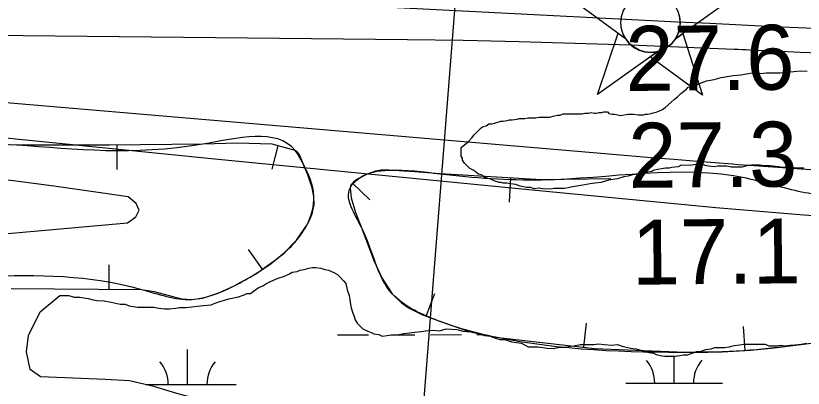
# Model space of a CAD drawing. Extents: x 3361039 to 3398939, y 576572 to 602007.
# Drawn here: x 3381254 to 3382066, y 585360 to 585744 of the extents above; entities that cross this region are included whole.
import ezdxf

# ---------------------------------------------------------------- set-up
doc = ezdxf.new("R2010")
doc.units = 0
for name, color, linetype in [('V-BORW-LINE', 7, 'Continuous'), ('V-CHAN-NAID', 7, 'Continuous'), ('V-RIVR-RANG', 7, 'Continuous'), ('V-SITE-VEGE', 7, 'Continuous'), ('V-TOPO-MAJR', 7, 'Continuous'), ('V-TOPO-MINR', 7, 'Continuous'), ('V-WETL-SWMP', 7, 'Continuous')]:
    doc.layers.add(name, color=color, linetype=linetype)

msp = doc.modelspace()

# ---------------------------------------------------------------- linework, layer by layer
at = {"layer": 'V-BORW-LINE'}
for p, q in [((3381357.75, 585610.77), (3381358.02, 585585.77)), ((3381524.08, 585610.05), (3381517.68, 585585.89)), ((3381601.07, 585571.69), (3381618.95, 585554.22)), ((3381764.16, 585576.87), (3381762.71, 585551.91)), ((3381508.14, 585482.73), (3381493.76, 585503.19)), ((3381349.92, 585462.11), (3381350.05, 585487.11)), ((3381676.92, 585434.33), (3381686.07, 585457.6)), ((3381839.57, 585402.24), (3381842.4, 585427.08)), ((3382005.98, 585398.71), (3382004.47, 585423.66))]:
    msp.add_line(p, q, dxfattribs=at)
for points in [[(3381248.73, 585462.66), (3381383.19, 585461.93), (3381396.24, 585459.77), (3381415.66, 585454.41), (3381425.33, 585452.32), (3381435, 585451.58), (3381446.12, 585452.88), (3381462.55, 585458.05), (3381478.78, 585465.47), (3381501.04, 585477.75), (3381521.69, 585492.26), (3381530.96, 585500.05), (3381543.15, 585512.8), (3381553.85, 585528.16), (3381557.61, 585535.53), (3381559.65, 585541.14), (3381561.33, 585549.58), (3381561.17, 585557.92), (3381559.37, 585566.77), (3381555.01, 585579.98), (3381549.36, 585593.15), (3381546.57, 585600.25), (3381544.67, 585603.3), (3381543.37, 585604.48), (3381541.77, 585605.37), (3381518.01, 585611.66), (3381482.27, 585612.98), (3381446.45, 585611.73), (3381350.4, 585610.69), (3381254.35, 585610.74), (3381248.84, 585611.13)], [(3381867.63, 585576.1), (3381796, 585575.03), (3381743.77, 585578.05), (3381691.54, 585581.2), (3381664.99, 585583.08), (3381638.45, 585584.98), (3381630.52, 585584.79), (3381624.68, 585583.76), (3381616.01, 585580.87), (3381607.38, 585576.47), (3381604.2, 585574.42), (3381602.03, 585572.67), (3381600.63, 585571.24), (3381599.11, 585568.92), (3381598.51, 585566.36), (3381599.48, 585556.45), (3381604.07, 585541.34), (3381610.08, 585526.4), (3381623.21, 585490.87), (3381631.16, 585473.72), (3381641.99, 585457.34), (3381651.47, 585447.98), (3381659.47, 585442.52), (3381672.5, 585436.07), (3381686.19, 585430.69), (3381717.08, 585419.85), (3381748.69, 585412.56), (3381850.72, 585400.97), (3381952.89, 585396.92), (3381982.29, 585397.28), (3382011.65, 585399.05), (3382036.2, 585401.7), (3382060.7, 585404.53), (3382143.48, 585415.45)]]:
    msp.add_lwpolyline(points, dxfattribs=at)
for points in [[(3380614.71, 585699.37), (3380933.86, 585658.54), (3380993.04, 585639.95), (3381254.35, 585610.74), (3381446.45, 585611.73), (3381541.77, 585605.37), (3381549.36, 585593.15), (3381561.17, 585557.92), (3381553.85, 585528.16), (3381521.69, 585492.26), (3381478.78, 585465.47), (3381435, 585451.58), (3381383.19, 585461.93), (3381059.18, 585470.07), (3380726.36, 585534.4), (3380328.5, 585584.44), (3380211.56, 585609.24), (3380158.59, 585613.34), (3380106.57, 585620.06), (3380047.44, 585636.22), (3380016.16, 585668.36), (3379997.02, 585709.42), (3379989.83, 585740.01), (3380003.9, 585755.26), (3380025.63, 585764.58), (3380071.77, 585772.23), (3380236.06, 585747.23), (3380349.15, 585718.45), (3380401.48, 585706.99), (3380505.12, 585707.23), (3380614.71, 585699.37)], [(3382571.75, 585529.85), (3382288.5, 585546.28), (3382119.28, 585556.22), (3382064.39, 585562.69), (3382006.96, 585576.93), (3381796, 585575.03), (3381691.54, 585581.2), (3381638.45, 585584.98), (3381607.38, 585576.47), (3381598.51, 585566.36), (3381610.08, 585526.4), (3381641.99, 585457.34), (3381686.19, 585430.69), (3381748.69, 585412.56), (3381952.89, 585396.92), (3382011.65, 585399.05), (3382060.7, 585404.53), (3382233.38, 585410.22), (3382597.39, 585393.13), (3382822.43, 585377.96), (3382985.12, 585375.03), (3383040.48, 585369.32), (3383111.3, 585349.64), (3383186.01, 585343.18), (3383349.37, 585344.09), (3383670.1, 585328.99), (3383776.96, 585325.83), (3383950.1, 585282.41), (3384048.66, 585281.9), (3384105.28, 585326.49), (3384120.75, 585332.34), (3384160.48, 585298.98), (3384209.82, 585275.27), (3384267.65, 585259.58), (3384373.27, 585255.57), (3384419.94, 585258.58), (3384709.73, 585239.38), (3384826.34, 585210.62), (3384946.51, 585203.35), (3385109.52, 585215.5), (3385207.25, 585213.25), (3385246.28, 585211.98), (3385305.12, 585207.81), (3385479.9, 585187.69), (3385835.24, 585189.26), (3386014.23, 585230.05), (3386056.71, 585240.88), (3386176.62, 585300.03), (3386207.38, 585325.51), (3386221.37, 585345.61), (3386182.35, 585376.31), (3386126.76, 585381.36), (3386029.51, 585369.17), (3385921.06, 585366.42), (3385817.08, 585354.08), (3385761.67, 585353.52), (3385594.41, 585354.59), (3385499.8, 585346.62), (3385375.62, 585344.42), (3385091.32, 585358.84), (3384912.21, 585381.83), (3384861.67, 585385.98), (3384294.69, 585385.71), (3384190.67, 585395.62), (3384128.27, 585377.4), (3384079.07, 585402.54), (3383956.19, 585439.51), (3383615.98, 585443.36), (3383292.93, 585470.42), (3383014.82, 585493.71), (3382867.4, 585507.63), (3382640.11, 585523.01), (3382571.75, 585529.85)]]:
    msp.add_spline(points, degree=3, dxfattribs=at)
at = {"layer": 'V-CHAN-NAID'}
for points in [[(3381821.1, 585766.19), (3381882.67, 585720.79), (3381881.55, 585722.7), (3381880.74, 585724.33), (3381879.92, 585726.3), (3381879.22, 585728.35), (3381878.86, 585729.67), (3381878.5, 585731.3), (3381878.25, 585732.74), (3381878.06, 585734.34), (3381877.95, 585736.08), (3381877.94, 585737.66), (3381878.05, 585739.73), (3381878.23, 585741.35), (3381878.62, 585743.55), (3381879.1, 585745.48)], [(3381996.26, 585764.95), (3381934.06, 585720.43), (3381934.97, 585721.91), (3381935.95, 585723.76), (3381936.66, 585725.35), (3381937.4, 585727.3), (3381937.94, 585729.09), (3381938.34, 585730.73), (3381938.7, 585732.74), (3381938.89, 585734.31), (3381939.01, 585736.51), (3381938.98, 585738.58), (3381938.79, 585740.8), (3381938.53, 585742.55), (3381938.04, 585744.79)]]:
    msp.add_lwpolyline(points, dxfattribs=at)
for points in [[(3381916.02, 585707.52), (3381853.82, 585663), (3381874.95, 585726.48), (3381882.67, 585720.79), (3381883.3, 585719.83), (3381884.68, 585717.97), (3381885.9, 585716.55), (3381887.36, 585715.05), (3381888.75, 585713.8), (3381890.21, 585712.64), (3381891.61, 585711.65), (3381893.29, 585710.62), (3381895, 585709.71), (3381896.79, 585708.9), (3381898.24, 585708.34), (3381899.87, 585707.81), (3381902.09, 585707.25), (3381903.62, 585706.96), (3381905.65, 585706.7), (3381907.19, 585706.6), (3381909.05, 585706.58), (3381910.73, 585706.66), (3381912.45, 585706.83), (3381914.35, 585707.14)], [(3381934.06, 585720.43), (3381941.85, 585726.01), (3381962.08, 585662.23), (3381908.23, 585701.94), (3381916.02, 585707.52), (3381917.69, 585708), (3381919.3, 585708.56), (3381921.46, 585709.47), (3381923.2, 585710.35), (3381925.06, 585711.47), (3381926.8, 585712.68), (3381928.35, 585713.92), (3381929.64, 585715.09), (3381931.02, 585716.51), (3381932.23, 585717.91), (3381933.35, 585719.39)]]:
    msp.add_lwpolyline(points, close=True, dxfattribs=at)
msp.add_circle((3381908.48, 585737.11), 30.54, dxfattribs=at)
at = {"layer": 'V-RIVR-RANG'}
msp.add_line((3381667.9, 585260.79), (3381771, 586569.73), dxfattribs=at)
at = {"layer": 'V-SITE-VEGE'}
for points in [[(3381805.26, 585565.46), (3381797.26, 585565.52), (3381793.62, 585566.27), (3381788.53, 585565.58), (3381784.9, 585567.06), (3381780.54, 585567.09), (3381774, 585568.59), (3381769.65, 585570.08), (3381763.83, 585570.84), (3381760.2, 585571.6), (3381756.56, 585571.62), (3381754.39, 585572.36), (3381752.2, 585572.38), (3381747.12, 585573.87), (3381744.23, 585575.34), (3381739.87, 585576.83), (3381736.96, 585577.58), (3381734.8, 585579.78), (3381730.44, 585581.26), (3381727.55, 585583.47), (3381725.38, 585584.93), (3381721.76, 585587.14), (3381716.7, 585592.27), (3381714.54, 585595.19), (3381714.55, 585597.38), (3381713.11, 585599.57), (3381713.18, 585608.3), (3381720.49, 585614.07), (3381724.16, 585618.4), (3381726.36, 585621.3), (3381733.69, 585628.52), (3381735.88, 585629.96), (3381738.79, 585630.67), (3381741.72, 585632.83), (3381744.62, 585632.81), (3381747.54, 585633.52), (3381754.1, 585635.65), (3381756.29, 585635.64), (3381760.66, 585636.33), (3381762.84, 585637.05), (3381765.75, 585637.03), (3381770.85, 585637.72), (3381773.04, 585638.43), (3381778.85, 585638.39), (3381781.77, 585639.09), (3381789.77, 585639.04), (3381793.41, 585639.74), (3381804.32, 585639.67), (3381809.43, 585641.09), (3381812.34, 585641.79), (3381815.25, 585641.77), (3381818.17, 585643.21), (3381823.26, 585643.17), (3381830.54, 585643.12), (3381837.81, 585643.07), (3381840.73, 585643.78), (3381844.36, 585643.75), (3381847.28, 585644.46), (3381850.18, 585643.71), (3381852.36, 585643.69), (3381855.28, 585644.4), (3381858.19, 585644.38), (3381860.37, 585645.09), (3381864.01, 585645.07), (3381865.46, 585643.6), (3381868.36, 585642.85), (3381871.27, 585642.83), (3381877.81, 585641.33), (3381885.09, 585642.74), (3381890.91, 585642.7), (3381895.99, 585641.93), (3381901.09, 585641.9), (3381903.27, 585642.61), (3381905.46, 585642.59), (3381909.1, 585643.3), (3381911.29, 585644.01), (3381914.2, 585644.71), (3381917.85, 585646.15), (3381920.77, 585647.58), (3381923.69, 585649.74), (3381929.55, 585654.79), (3381933.21, 585658.4), (3381936.14, 585660.57), (3381939.8, 585664.18), (3381945.65, 585668.5), (3381947.12, 585670.67), (3381950.03, 585671.38), (3381956.6, 585673.51), (3381966.07, 585677.09), (3381974.09, 585678.48), (3381981.38, 585680.61), (3381993.76, 585682.71), (3382001.76, 585683.38), (3382013.42, 585685.48), (3382020.69, 585684.7), (3382027.97, 585685.38), (3382041.79, 585685.28), (3382047.61, 585685.97), (3382056.34, 585686.64), (3382062.89, 585687.32), (3382070.17, 585687.27)], [(3382066.55, 585586.91), (3382060.01, 585586.95), (3382053.47, 585587.72), (3382044.01, 585587.79), (3382040.38, 585588.55), (3382031.66, 585589.33), (3382026.56, 585589.37), (3382020.75, 585590.14), (3382012.75, 585590.19), (3382007.65, 585589.5), (3382002.55, 585588.08), (3381991.64, 585588.16), (3381987.28, 585588.92), (3381982.19, 585588.95), (3381977.82, 585588.98), (3381974.18, 585588.28), (3381968.37, 585589.05), (3381964.74, 585589.8), (3381961.84, 585591.28), (3381956.74, 585591.31), (3381949.46, 585589.91), (3381940.01, 585589.98), (3381937.09, 585588.55), (3381930.53, 585587.86), (3381927.62, 585587.15), (3381923.98, 585587.18), (3381919.61, 585586.48), (3381912.33, 585585.08), (3381909.41, 585583.64), (3381905.77, 585582.94), (3381902.85, 585582.23), (3381898.48, 585581.54), (3381895.57, 585580.83), (3381889.74, 585580.15), (3381885.37, 585578.72), (3381881, 585578.02), (3381874.44, 585575.89), (3381864.97, 585574.5), (3381857.68, 585572.37), (3381851.13, 585571.69), (3381846.03, 585570.99), (3381838.75, 585569.59), (3381826.37, 585567.49), (3381823.45, 585566.79), (3381819.81, 585566.09), (3381808.9, 585566.16), (3381805.26, 585565.46)]]:
    msp.add_lwpolyline(points, dxfattribs=at)
at = {"layer": 'V-TOPO-MAJR'}
for points in [[(3381161.75, 585725.12), (3381657.79, 585719.95), (3381715.33, 585719.1), (3381772.87, 585717.9), (3381830.39, 585716.2), (3381887.9, 585714.15), (3381994.59, 585709.88), (3381998.75, 585709.71), (3382002.9, 585709.53), (3382007.06, 585709.35), (3382011.22, 585709.16), (3382042.9, 585707.69), (3382062.9, 585706.85), (3382082.91, 585706.15), (3382102.92, 585705.65), (3382122.93, 585705.27), (3382747.59, 585696.63)], [(3382698.48, 585541.49), (3382673.17, 585543.09), (3382647.87, 585544.79), (3382015.38, 585589.3), (3382009.82, 585589.7), (3382004.27, 585590.11), (3381998.72, 585590.54), (3381993.17, 585590.98), (3381956.66, 585593.92), (3381932.86, 585595.86), (3381909.06, 585597.82), (3381885.26, 585599.81), (3381861.47, 585601.82), (3381118.58, 585665.15)]]:
    msp.add_lwpolyline(points, dxfattribs=at)
at = {"layer": 'V-TOPO-MINR'}
for points in [[(3381250.37, 585773.58), (3381936.29, 585738.19), (3381969.46, 585736.53), (3382002.62, 585734.93), (3382035.8, 585733.41), (3382068.97, 585731.94), (3382169.28, 585727.61), (3382252.62, 585724.39), (3382335.98, 585721.68), (3382419.35, 585719.73), (3382502.74, 585718.29), (3382766.07, 585714.94), (3382782.34, 585714.87), (3382798.6, 585714.98), (3382814.87, 585715.36), (3382831.13, 585715.93), (3383003.12, 585723.36), (3383095.43, 585727.56), (3383187.73, 585732.03), (3383280, 585736.93), (3383372.26, 585742.11), (3383493.4, 585749.18), (3383525.07, 585751.08), (3384501.3, 585871.43)], [(3382750.72, 585498.83), (3382481.83, 585511.84), (3382402.26, 585516), (3382322.71, 585520.58), (3382243.21, 585525.79), (3382163.73, 585531.41), (3382062.6, 585538.96), (3382033.71, 585541.21), (3382004.83, 585543.58), (3381975.97, 585546.14), (3381947.12, 585548.83), (3381786.43, 585564.32), (3381677.26, 585574.91), (3381568.08, 585585.59), (3381458.93, 585596.39), (3381349.78, 585607.29), (3381150.91, 585627.26)], [(3381168.01, 585512.54), (3381368.77, 585530.48), (3381377.32, 585536.95), (3381381.09, 585543.57), (3381377.71, 585550.39), (3381369.55, 585557.34), (3381328.93, 585563.35), (3381292.73, 585568.48), (3381256.49, 585573.33), (3381220.2, 585577.74)]]:
    msp.add_lwpolyline(points, dxfattribs=at)
at = {"layer": 'V-WETL-SWMP'}
for p, q in [((3381585.36, 585414.88), (3381617.36, 585414.97)), ((3381641.04, 585415.03), (3381665.36, 585415.1)), ((3381681.36, 585415.15), (3381713.36, 585415.23)), ((3381729.36, 585415.28), (3381734.38, 585415.29)), ((3381430.91, 585363.71), (3381430.81, 585399.71)), ((3381932.81, 585365.1), (3381932.74, 585392.99)), ((3381387.96, 585363.59), (3381480.91, 585363.85)), ((3381882.82, 585364.96), (3381982.81, 585365.24))]:
    msp.add_line(p, q, dxfattribs=at)
for points in [[(3381396.16, 585361.7), (3381371.08, 585367.46), (3381345.98, 585369.04), (3381279.01, 585371.6), (3381268.6, 585379.34), (3381264.54, 585397.52), (3381266.75, 585414.24), (3381278.79, 585438.58), (3381298.94, 585455.58), (3381308.27, 585455.51), (3381314, 585454.04), (3381319.74, 585454), (3381328.34, 585452.5), (3381333.36, 585451.03), (3381337.66, 585450.28), (3381344.84, 585450.23), (3381352, 585448.75), (3381361.32, 585446.53), (3381366.34, 585446.49), (3381370.64, 585445.03), (3381379.24, 585443.53), (3381385.7, 585443.48), (3381395.75, 585443.42), (3381401.49, 585442.66), (3381407.22, 585441.9), (3381412.25, 585441.86), (3381418.71, 585442.54), (3381422.31, 585443.23), (3381428.77, 585443.18), (3381435.23, 585443.85), (3381440.98, 585444.53), (3381447.44, 585445.2), (3381455.34, 585445.87), (3381458.22, 585447.28), (3381463.98, 585449.4), (3381469.02, 585450.8), (3381473.33, 585452.2), (3381483.4, 585454.28), (3381489.15, 585456.4), (3381492.03, 585457.81), (3381495.62, 585457.79), (3381499.95, 585460.63), (3381503.56, 585463.47), (3381508.6, 585465.59), (3381511.48, 585467.72), (3381515.8, 585469.85), (3381519.4, 585471.26), (3381524.44, 585473.38), (3381530.92, 585475.48), (3381535.24, 585477.61), (3381538.84, 585479.73), (3381543.87, 585480.42), (3381546.75, 585481.83), (3381551.06, 585482.52), (3381556.1, 585483.92), (3381559.69, 585484.61), (3381563.28, 585484.59), (3381568.3, 585483.84), (3381572.6, 585482.37), (3381576.18, 585481.63), (3381581.91, 585479.43), (3381585.48, 585477.26), (3381588.33, 585474.36), (3381591.89, 585470.75), (3381594.03, 585467.86), (3381595.42, 585461.4), (3381597.53, 585455.64), (3381598.22, 585451.33), (3381598.9, 585446.3), (3381599.59, 585442.7), (3381601, 585438.39), (3381602.41, 585434.79), (3381603.81, 585430.47), (3381605.94, 585426.87), (3381609.51, 585423.25)], [(3381609.51, 585423.25), (3381611.64, 585421.08), (3381616.65, 585418.9), (3381620.23, 585417.44), (3381623.09, 585415.98), (3381628.11, 585415.23), (3381631.69, 585413.77), (3381636.72, 585414.45), (3381641.75, 585415.13), (3381646.77, 585415.1), (3381653.96, 585416.48), (3381659.71, 585417.16), (3381665.45, 585417.84), (3381671.92, 585418.51), (3381676.23, 585419.2), (3381684.13, 585419.86), (3381690.58, 585419.1), (3381697.78, 585421.2), (3381708.54, 585420.41), (3381714.99, 585418.93), (3381722.88, 585418.15), (3381732.19, 585415.93), (3381737.21, 585414.46), (3381742.95, 585413.7), (3381748.67, 585411.51), (3381752.97, 585410.05), (3381757.99, 585410.01), (3381765.15, 585407.81), (3381770.17, 585407.05), (3381775.19, 585406.3), (3381782.35, 585402.66), (3381787.37, 585402.63), (3381792.39, 585402.59), (3381801.71, 585401.09), (3381808.17, 585401.05), (3381815.36, 585402.43), (3381820.39, 585402.4), (3381823.98, 585403.09), (3381829.01, 585403.77), (3381836.2, 585405.16), (3381841.22, 585405.12), (3381849.83, 585405.06), (3381854.86, 585405.74), (3381860.6, 585404.98), (3381868.49, 585404.21), (3381874.23, 585404.89), (3381879.25, 585403.42), (3381887.85, 585401.2), (3381893.58, 585400.45), (3381899.32, 585398.97), (3381907.2, 585396.76), (3381911.5, 585396.01), (3381914.36, 585394.56), (3381918.66, 585393.81), (3381922.96, 585393.06), (3381927.98, 585393.03), (3381933.73, 585392.99), (3381938.76, 585393.67), (3381942.35, 585394.36), (3381946.66, 585394.33), (3381952.41, 585396.45), (3381956.01, 585397.86), (3381959.6, 585397.83), (3381965.36, 585399.94), (3381971.1, 585400.62), (3381974.7, 585402.03), (3381981.16, 585401.99), (3381984.75, 585401.96), (3381989.78, 585402.64), (3381994.81, 585404.04), (3382000.56, 585404.72), (3382004.87, 585405.41), (3382008.46, 585405.38), (3382013.49, 585405.35), (3382021.38, 585405.29), (3382026.41, 585405.26), (3382030.7, 585403.79), (3382038.6, 585403.74), (3382042.19, 585404.43), (3382047.93, 585403.67), (3382052.24, 585404.36), (3382055.83, 585404.33), (3382061.58, 585405.01), (3382065.89, 585405.7), (3382069.48, 585406.39)], [(3384399.98, 585174.59), (3384351.14, 585174.93), (3384302.26, 585169.69), (3384258.29, 585168.6), (3384214.33, 585167.51), (3384171.08, 585169.21), (3384126.46, 585174.41), (3384039.29, 585179.91), (3383859.33, 585188.14), (3383701.01, 585197.63), (3383558.73, 585204.9), (3383336.97, 585221.81), (3383114.47, 585233.83), (3382849.44, 585248.95), (3382638.15, 585266.48), (3382416.37, 585279.9), (3382178.58, 585299.7), (3382002.11, 585307.92), (3381790.8, 585322.66), (3381691.06, 585327.54), (3381512.52, 585338.56), (3381459.53, 585343.82), (3381419.83, 585354.56), (3381396.16, 585361.7)]]:
    msp.add_lwpolyline(points, dxfattribs=at)
for centre, start, end in [((3381375.66, 585364.03), 359.38648, 40.93014), ((3381486.15, 585364.34), 139.38648, 180.93013), ((3381877.57, 585365.42), 359.38648, 40.93014), ((3381988.06, 585365.73), 139.38648, 180.93013)]:
    msp.add_arc(centre, 35.25, start, end, dxfattribs=at)

# ---------------------------------------------------------------- texts
at = {"layer": 'V-RIVR-RANG'}
for s, p in [('27.6', (3381882.76, 585666.63)), ('27.3', (3381885.75, 585566.65)), ('17.1', (3381889.27, 585466.68))]:
    msp.add_text(s, height=67, rotation=0.51833, dxfattribs=at).set_placement(p)

doc.saveas('drawing.dxf')
